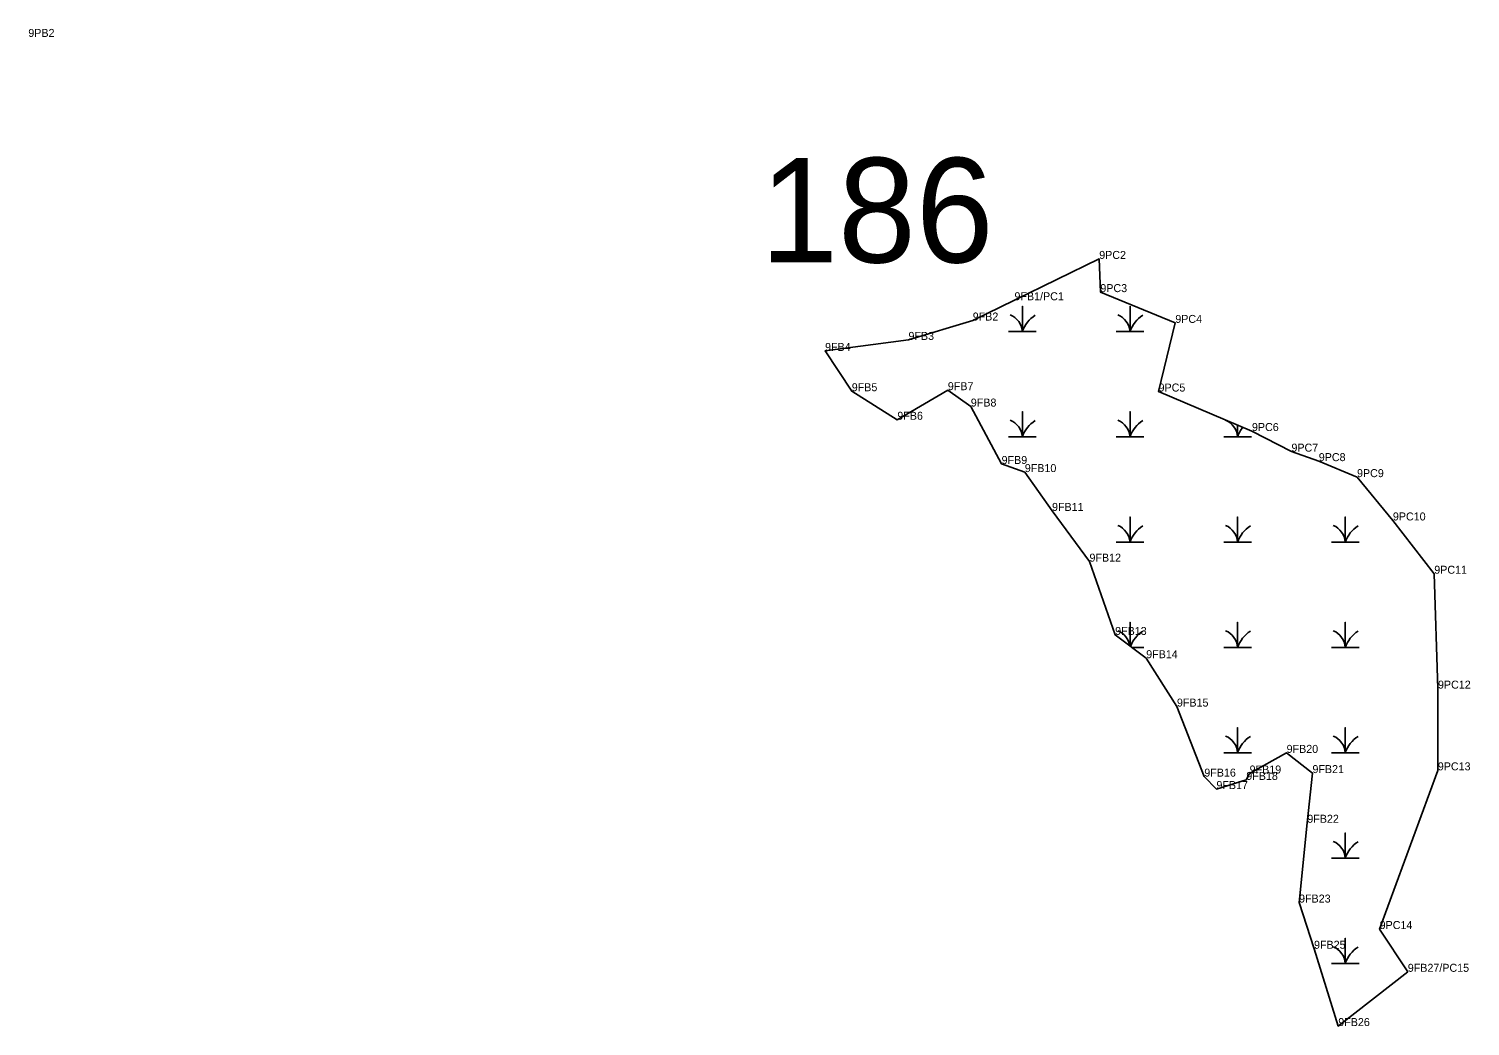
# Model space of a CAD drawing. Extents: x 2072529 to 2268796, y 436423 to 470406.
# Drawn here: x 2214923 to 2215823, y 450195 to 450819 of the extents above; entities that cross this region are included whole.
import ezdxf

# ---------------------------------------------------------------- set-up
doc = ezdxf.new("R2010")
doc.units = 0
for name, color, linetype in [('Default', 7, 'Continuous'), ('Exist Environmental Wetland Boundary Cogo Comment', 7, 'Continuous'), ('Exist Environmental Wetland Boundary Cogo Point CELL', 7, 'Continuous'), ('Old_Level_20', 7, 'Continuous')]:
    doc.layers.add(name, color=color, linetype=linetype)

msp = doc.modelspace()

# ---------------------------------------------------------------- linework, layer by layer
at = {"layer": 'Exist Environmental Wetland Boundary Cogo Point CELL'}
for points in [[(2215534.94, 450629.42), (2215543.54, 450629.42), (2215543.54, 450645.2), (2215543.54, 450629.42), (2215552.14, 450629.42)], [(2215602.19, 450629.42), (2215610.79, 450629.42), (2215610.79, 450645.2), (2215610.79, 450629.42), (2215619.39, 450629.42)], [(2215534.94, 450563.62), (2215543.54, 450563.62), (2215543.54, 450579.4), (2215543.54, 450563.62), (2215552.14, 450563.62)], [(2215602.19, 450563.62), (2215610.79, 450563.62), (2215610.79, 450579.4), (2215610.79, 450563.62), (2215619.39, 450563.62)], [(2215669.44, 450563.62), (2215678.04, 450563.62), (2215678.04, 450571.04)], [(2215678.04, 450571.04), (2215678.04, 450563.62), (2215686.64, 450563.62)], [(2215602.19, 450497.82), (2215610.79, 450497.82), (2215610.79, 450513.6), (2215610.79, 450497.82), (2215619.39, 450497.82)], [(2215669.44, 450497.82), (2215678.04, 450497.82), (2215678.04, 450513.6), (2215678.04, 450497.82), (2215686.64, 450497.82)], [(2215736.69, 450497.82), (2215745.29, 450497.82), (2215745.29, 450513.6), (2215745.29, 450497.82), (2215753.89, 450497.82)], [(2215610.79, 450432.91), (2215610.79, 450447.8), (2215610.79, 450432.91)], [(2215669.44, 450432.02), (2215678.04, 450432.02), (2215678.04, 450447.8), (2215678.04, 450432.02), (2215686.64, 450432.02)], [(2215736.69, 450432.02), (2215745.29, 450432.02), (2215745.29, 450447.8), (2215745.29, 450432.02), (2215753.89, 450432.02)], [(2215611.97, 450432.02), (2215619.39, 450432.02)], [(2215669.44, 450366.22), (2215678.04, 450366.22), (2215678.04, 450382), (2215678.04, 450366.22), (2215686.64, 450366.22)], [(2215736.69, 450366.22), (2215745.29, 450366.22), (2215745.29, 450382), (2215745.29, 450366.22), (2215753.89, 450366.22)], [(2215736.69, 450300.42), (2215745.29, 450300.42), (2215745.29, 450316.2), (2215745.29, 450300.42), (2215753.89, 450300.42)], [(2215736.69, 450234.62), (2215745.29, 450234.62), (2215745.29, 450250.4), (2215745.29, 450234.62), (2215753.89, 450234.62)]]:
    msp.add_lwpolyline(points, dxfattribs=at)
for centre, radius, start, end in [((2215531.27, 450628.53), 12.3, 4.14034, 67.53497), ((2215561.78, 450623.36), 19.22, 122.12745, 161.62219), ((2215598.52, 450628.53), 12.3, 4.14034, 67.53497), ((2215629.03, 450623.36), 19.22, 122.12745, 161.62219), ((2215531.27, 450562.73), 12.3, 4.14034, 67.53497), ((2215561.78, 450557.56), 19.22, 122.12745, 161.62219), ((2215598.52, 450562.73), 12.3, 4.14034, 67.53497), ((2215629.03, 450557.56), 19.22, 122.12745, 161.62219), ((2215665.77, 450562.73), 12.3, 4.14034, 67.53497), ((2215696.28, 450557.56), 19.22, 141.03586, 161.62219), ((2215598.52, 450496.93), 12.3, 4.14034, 67.53497), ((2215629.03, 450491.76), 19.22, 122.12745, 161.62219), ((2215665.77, 450496.93), 12.3, 4.14034, 67.53497), ((2215696.28, 450491.76), 19.22, 122.12745, 161.62219), ((2215733.02, 450496.93), 12.3, 4.14034, 67.53497), ((2215763.53, 450491.76), 19.22, 122.12745, 161.62219), ((2215598.52, 450431.13), 12.3, 8.68347, 67.53497), ((2215629.03, 450425.96), 19.22, 122.12745, 159.40412), ((2215665.77, 450431.13), 12.3, 4.14034, 67.53497), ((2215696.28, 450425.96), 19.22, 122.12745, 161.62219), ((2215733.02, 450431.13), 12.3, 4.14034, 67.53497), ((2215763.53, 450425.96), 19.22, 122.12745, 161.62219), ((2215665.77, 450365.33), 12.3, 4.14034, 67.53497), ((2215696.28, 450360.16), 19.22, 122.12745, 161.62219), ((2215733.02, 450365.33), 12.3, 4.14034, 67.53497), ((2215763.53, 450360.16), 19.22, 122.12745, 161.62219), ((2215733.02, 450299.53), 12.3, 4.14034, 67.53497), ((2215763.53, 450294.36), 19.22, 122.12745, 161.62219), ((2215733.02, 450233.73), 12.3, 4.14034, 67.53497), ((2215763.53, 450228.56), 19.22, 122.12745, 161.62219)]:
    msp.add_arc(centre, radius, start, end, dxfattribs=at)
at = {"layer": 'Old_Level_20'}
for p, q in [((2215591.55, 450674.79), (2215591.55, 450674.79)), ((2215592.26, 450654.07), (2215592.26, 450654.07)), ((2215538.62, 450648.97), (2215538.62, 450648.97)), ((2215512.54, 450636.31), (2215512.54, 450636.31)), ((2215639.08, 450634.8), (2215639.08, 450634.8)), ((2215420.29, 450617.31), (2215420.29, 450617.31)), ((2215472.39, 450624.19), (2215472.39, 450624.19)), ((2215436.97, 450592.12), (2215436.97, 450592.12)), ((2215496.98, 450592.79), (2215496.98, 450592.79)), ((2215628.63, 450591.94), (2215628.63, 450591.94)), ((2215511.35, 450582.55), (2215511.35, 450582.55)), ((2215465.43, 450574.31), (2215465.43, 450574.31)), ((2215686.97, 450567.26), (2215686.97, 450567.26)), ((2215711.64, 450554.39), (2215711.64, 450554.39)), ((2215530.57, 450546.67), (2215530.57, 450546.67)), ((2215728.71, 450548.46), (2215728.71, 450548.46)), ((2215545.07, 450541.63), (2215545.07, 450541.63)), ((2215752.6, 450538.46), (2215752.6, 450538.46)), ((2215562.08, 450517.35), (2215562.08, 450517.35)), ((2215775.02, 450511.41), (2215775.02, 450511.41)), ((2215585.47, 450485.65), (2215585.47, 450485.65)), ((2215800.86, 450478.1), (2215800.86, 450478.1)), ((2215601.5, 450439.86), (2215601.5, 450439.86)), ((2215620.9, 450425.34), (2215620.9, 450425.34)), ((2215803.18, 450406.31), (2215803.18, 450406.31)), ((2215640.09, 450395.1), (2215640.09, 450395.1)), ((2215708.62, 450366.17), (2215708.62, 450366.17)), ((2215657.2, 450351.33), (2215657.2, 450351.33)), ((2215683.43, 450349.27), (2215683.43, 450349.27)), ((2215685.51, 450353.29), (2215685.51, 450353.29)), ((2215724.76, 450353.54), (2215724.76, 450353.54)), ((2215803.07, 450355.25), (2215803.07, 450355.25)), ((2215664.78, 450343.58), (2215664.78, 450343.58)), ((2215721.55, 450322.51), (2215721.55, 450322.51)), ((2215716.41, 450272.64), (2215716.41, 450272.64)), ((2215766.74, 450256.11), (2215766.74, 450256.11)), ((2215725.74, 450243.79), (2215725.74, 450243.79)), ((2215784.32, 450229.39), (2215784.32, 450229.39)), ((2215740.89, 450195.49), (2215740.89, 450195.49))]:
    msp.add_line(p, q, dxfattribs=at)
msp.add_lwpolyline([(2215538.62, 450648.97), (2215591.55, 450674.79), (2215592.26, 450654.07), (2215639.08, 450634.8), (2215628.63, 450591.94), (2215686.97, 450567.26), (2215711.64, 450554.39), (2215728.71, 450548.46), (2215752.6, 450538.46), (2215775.02, 450511.41), (2215800.86, 450478.1), (2215803.18, 450406.31), (2215803.07, 450355.25), (2215766.74, 450256.11), (2215784.32, 450229.39), (2215740.89, 450195.49), (2215725.74, 450243.79), (2215716.41, 450272.64), (2215721.55, 450322.51), (2215724.76, 450353.54), (2215708.62, 450366.17), (2215685.51, 450353.29), (2215683.43, 450349.27), (2215664.78, 450343.58), (2215657.2, 450351.33), (2215640.09, 450395.1), (2215620.9, 450425.34), (2215601.5, 450439.86), (2215585.47, 450485.65), (2215562.08, 450517.35), (2215545.07, 450541.63), (2215530.57, 450546.67), (2215511.35, 450582.55), (2215496.98, 450592.79), (2215465.43, 450574.31), (2215436.97, 450592.12), (2215420.29, 450617.31), (2215472.39, 450624.19), (2215512.54, 450636.31)], close=True, dxfattribs=at)

# ---------------------------------------------------------------- texts
at = {"layer": 'Default'}
msp.add_text('186', height=65.34, dxfattribs=at).set_placement((2215379.81, 450672.59))
at = {"layer": 'Exist Environmental Wetland Boundary Cogo Comment'}
for s, p in [('9PB2', (2214922.57, 450813.5)), ('9PC2', (2215591.55, 450674.79)), ('9FB1/PC1', (2215538.62, 450648.97)), ('9PC3', (2215592.26, 450654.07)), ('9FB2', (2215512.54, 450636.31)), ('9PC4', (2215639.08, 450634.8)), ('9FB3', (2215472.39, 450624.19)), ('9FB4', (2215420.29, 450617.31)), ('9FB5', (2215436.97, 450592.12)), ('9FB7', (2215496.98, 450592.79)), ('9PC5', (2215628.63, 450591.94)), ('9FB8', (2215511.35, 450582.55)), ('9FB6', (2215465.43, 450574.31)), ('9PC6', (2215686.97, 450567.26)), ('9PC7', (2215711.64, 450554.39)), ('9FB9', (2215530.57, 450546.67)), ('9FB10', (2215545.07, 450541.63)), ('9PC8', (2215728.71, 450548.46)), ('9PC9', (2215752.6, 450538.46)), ('9FB11', (2215562.08, 450517.35)), ('9PC10', (2215775.02, 450511.41)), ('9FB12', (2215585.47, 450485.65)), ('9PC11', (2215800.86, 450478.1)), ('9FB13', (2215601.5, 450439.86)), ('9FB14', (2215620.9, 450425.34)), ('9PC12', (2215803.18, 450406.31)), ('9FB15', (2215640.09, 450395.1)), ('9FB20', (2215708.62, 450366.17)), ('9FB16', (2215657.2, 450351.33)), ('9FB19', (2215685.51, 450353.29)), ('9FB21', (2215724.76, 450353.54)), ('9PC13', (2215803.07, 450355.25)), ('9FB17', (2215664.78, 450343.58)), ('9FB18', (2215683.43, 450349.27)), ('9FB22', (2215721.55, 450322.51)), ('9FB23', (2215716.41, 450272.64)), ('9PC14', (2215766.74, 450256.11)), ('9FB25', (2215725.74, 450243.79)), ('9FB27/PC15', (2215784.32, 450229.39)), ('9FB26', (2215740.89, 450195.49))]:
    msp.add_text(s, height=5, dxfattribs=at).set_placement(p)

doc.saveas('drawing.dxf')
